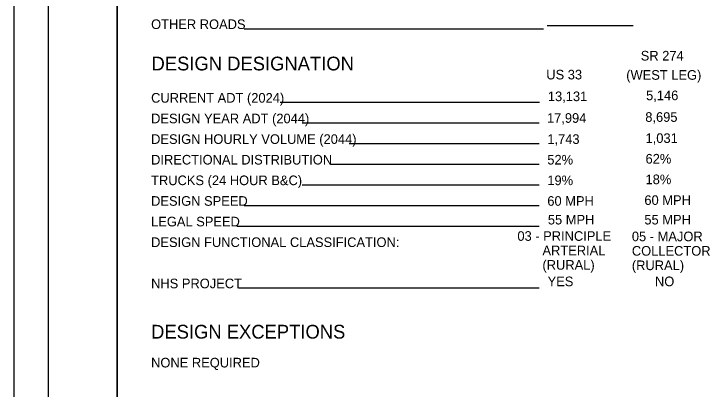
# Model space of a CAD drawing. Extents: x -5.9 to 34, y 0 to 22.
# Drawn here: x 0 to 10.13, y 5.64 to 11.1 of the extents above; entities that cross this region are included whole.
import ezdxf

# ---------------------------------------------------------------- set-up
doc = ezdxf.new("R2010")
doc.units = 0
for name, color, linetype in [('SH_Border', 7, 'Continuous'), ('SH_Cut_Line', 7, 'Continuous'), ('SH_Data', 7, 'Continuous'), ('SH_Text', 7, 'Continuous')]:
    doc.layers.add(name, color=color, linetype=linetype)

msp = doc.modelspace()

# ---------------------------------------------------------------- linework, layer by layer
at = {"layer": 'SH_Border'}
for points in [[(0.5, 21.5), (1.5, 21.5), (1.5, 0.5), (0.5, 0.5)], [(1.5, 21.5), (33.5, 21.5), (33.5, 0.5), (1.5, 0.5)]]:
    msp.add_lwpolyline(points, close=True, dxfattribs=at)
at = {"layer": 'SH_Cut_Line'}
msp.add_lwpolyline([(0, 0), (34, 0), (34, 22), (0, 22)], close=True, dxfattribs=at)
at = {"layer": 'SH_Data'}
for p, q in [((7.7, 10.877), (3.347, 10.877)), ((9, 10.922), (7.75, 10.922)), ((7.642, 9.806), (3.871, 9.806)), ((7.637, 9.506), (4.189, 9.506)), ((7.637, 9.206), (4.872, 9.206)), ((7.637, 8.906), (4.604, 8.906)), ((7.637, 8.606), (4.189, 8.606)), ((7.637, 8.306), (3.346, 8.306)), ((7.637, 8.006), (3.242, 8.006)), ((7.637, 7.106), (3.267, 7.106))]:
    msp.add_line(p, q, dxfattribs=at)

# ---------------------------------------------------------------- texts
msp.add_text('DESIGN DESIGNATION', height=0.2, dxfattribs=at).set_placement((2, 10.275))
at = {"layer": 'SH_Text'}
for s, height, p in [('OTHER ROADS', 0.14, (1.994, 10.877)), ('SR 274', 0.14, (9.112, 10.419)), ('US 33', 0.14, (7.739, 10.144)), ('(WEST LEG)', 0.14, (8.901, 10.139)), ('CURRENT ADT (2024)', 0.14, (1.994, 9.806)), ('13,131', 0.14, (7.762, 9.828)), ('5,146', 0.14, (9.19, 9.842)), ('DESIGN YEAR ADT (2044)', 0.14, (1.994, 9.506)), ('17,994', 0.14, (7.749, 9.513)), ('8,695', 0.14, (9.178, 9.527)), ('DESIGN HOURLY VOLUME (2044)', 0.14, (1.994, 9.206)), ('1,743', 0.14, (7.754, 9.206)), ('1,031', 0.14, (9.182, 9.22)), ('DIRECTIONAL DISTRIBUTION', 0.14, (1.994, 8.906)), ('52%', 0.14, (7.754, 8.906)), ('62%', 0.14, (9.182, 8.92)), ('TRUCKS (24 HOUR B&C)', 0.14, (1.994, 8.606)), ('19%', 0.14, (7.754, 8.606)), ('18%', 0.14, (9.182, 8.62)), ('DESIGN SPEED', 0.14, (1.994, 8.306)), ('60 MPH', 0.14, (7.754, 8.306)), ('60 MPH', 0.14, (9.165, 8.318)), ('LEGAL SPEED', 0.14, (1.994, 8.006)), ('55 MPH', 0.14, (7.762, 8.034)), ('55 MPH', 0.14, (9.165, 8.034)), ('03 - PRINCIPLE     ', 0.14, (7.319, 7.796)), ('05 - MAJOR ', 0.14, (8.983, 7.79)), ('DESIGN FUNCTIONAL CLASSIFICATION:', 0.14, (1.994, 7.706)), ('       ARTERIAL ', 0.14, (7.319, 7.586)), ('COLLECTOR ', 0.14, (8.983, 7.58)), ('       (RURAL)', 0.14, (7.319, 7.376)), ('(RURAL)', 0.14, (8.983, 7.37)), ('NHS PROJECT', 0.14, (1.994, 7.106)), ('YES', 0.14, (7.758, 7.136)), ('NO', 0.14, (9.319, 7.136)), ('DESIGN EXCEPTIONS', 0.2, (1.994, 6.374)), ('NONE REQUIRED', 0.14, (1.994, 5.954))]:
    msp.add_text(s, height=height, dxfattribs=at).set_placement(p)

doc.saveas('drawing.dxf')
